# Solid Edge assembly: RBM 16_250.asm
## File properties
Title: Zylinder
Author: ahadarics
Template: iso metric assembly.asm
Last saved by: ahadarics
Revision: 18
Application: Solid Edge
Username: ahadarics
Dokumentum tartalom típus: 1
Document Number: RBM 16/250
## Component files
Profilrohr.par
Kolbenstange.par
Kit.par
Mutter_1.par
Mutter_2.par
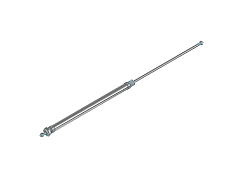
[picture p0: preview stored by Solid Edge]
